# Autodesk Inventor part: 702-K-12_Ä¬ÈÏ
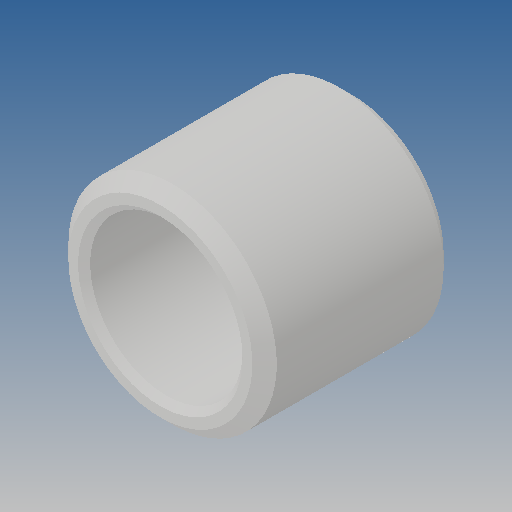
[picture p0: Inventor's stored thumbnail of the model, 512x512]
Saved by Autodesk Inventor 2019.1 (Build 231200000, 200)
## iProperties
Created: 2010-06
Part Number: 702-K-12_Ä¬ÈÏ
Material: Ogólny
Document SubType Name: Modeling
Designer: CADENGINEERING4
Density: 1 g/cm^3
Appearance: Domyślna
Author: CADENGINEERING4
Revision Number: ÈÎºÎ
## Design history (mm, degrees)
feature "NONE"
node "Bryła1"
